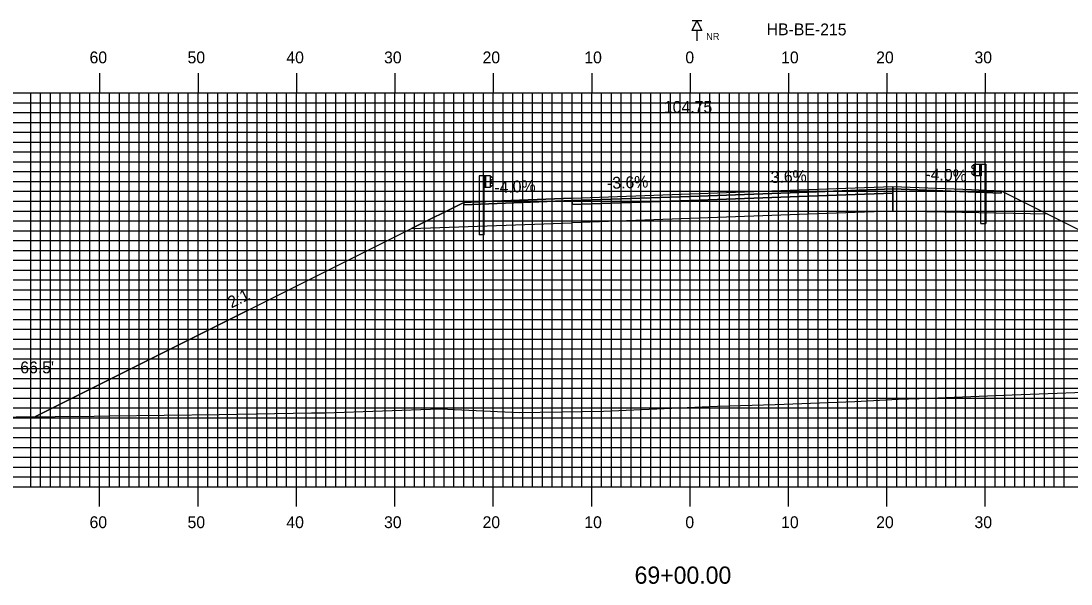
# Model space of a CAD drawing. Extents: x 1759823 to 1760167, y 442591 to 442811.
# Drawn here: x 1759921.2 to 1760027.9, y 442658.8 to 442716 of the extents above; entities that cross this region are included whole.
import ezdxf

# ---------------------------------------------------------------- set-up
doc = ezdxf.new("R2010")
doc.units = 0
for name, color, linetype in [('ANNOTATION', 7, 'Continuous'), ('BORING - NO REFUSAL', 7, 'Continuous'), ('D_Guardrail_Beam_Lt', 7, 'Continuous'), ('D_Guardrail_Beam_Rt', 7, 'Continuous'), ('D_Roadway_Centerline', 7, 'Continuous'), ('D_Roadway_Centerline_Text', 7, 'Continuous'), ('D_Roadway_Edge_Shoulder', 7, 'Continuous'), ('D_Roadway_Edge_TW', 7, 'Continuous'), ('D_Roadway_Pavement', 7, 'Continuous'), ('D_Roadway_SlopeLines', 7, 'Continuous'), ('D_Roadway_SubGrade', 7, 'Continuous'), ('D_Text_Standard', 7, 'Continuous'), ('H_V ANNOTATION', 7, 'Continuous'), ('MAJOR', 7, 'Continuous'), ('MINOR', 7, 'Continuous'), ('S_Roadway_Centerline', 7, 'Continuous')]:
    doc.layers.add(name, color=color, linetype=linetype)

msp = doc.modelspace()

# ---------------------------------------------------------------- linework, layer by layer
at = {"layer": 'BORING - NO REFUSAL'}
for p, q in [((1759990.37, 442715.97), (1759989.41, 442715.97)), ((1759989.89, 442715.01), (1759989.89, 442713.95))]:
    msp.add_line(p, q, dxfattribs=at)
msp.add_lwpolyline([(1759989.89, 442715.97), (1759990.37, 442715.01), (1759989.41, 442715.01)], close=True, dxfattribs=at)
at = {"layer": 'D_Guardrail_Beam_Lt'}
for p, q in [((1759967.76, 442700.25), (1759967.76, 442694.25)), ((1759968.23, 442700.25), (1759967.76, 442700.25)), ((1759968.92, 442700.25), (1759968.23, 442700.25)), ((1759968.23, 442700.25), (1759968.23, 442699.08)), ((1759968.29, 442700.25), (1759968.29, 442699.08)), ((1759968.4, 442700.25), (1759968.4, 442699.08)), ((1759968.92, 442699.08), (1759968.92, 442700.25)), ((1759968.92, 442700.16), (1759968.99, 442700.15)), ((1759969.15, 442699.9), (1759968.95, 442699.76)), ((1759969.01, 442700.14), (1759969.15, 442700.04)), ((1759968.23, 442699.08), (1759968.92, 442699.08)), ((1759968.25, 442694.25), (1759968.25, 442699.08)), ((1759968.92, 442699.7), (1759968.92, 442699.63)), ((1759968.99, 442699.18), (1759968.92, 442699.16)), ((1759968.95, 442699.56), (1759969.15, 442699.43)), ((1759969.15, 442699.28), (1759969.01, 442699.18)), ((1759968.25, 442694.25), (1759967.76, 442694.25))]:
    msp.add_line(p, q, dxfattribs=at)
for centre, major_axis, start_param, end_param in [((1759968.98, 442700.11), (0.0417, 0), 0.959931, 1.376053), ((1759969.1, 442699.97), (0.0877, 0), 5.323254, 7.243116), ((1759969, 442699.7), (-0.0789, 0), 5.323254, 6.283185), ((1759969, 442699.63), (-0.0789, 0), 6.283185, 7.243116), ((1759968.98, 442699.22), (0.0417, 0), 4.907132, 5.323254), ((1759969.1, 442699.36), (0.0877, 0), 5.323254, 7.243116)]:
    msp.add_ellipse(centre, major_axis=major_axis, ratio=0.995501, start_param=start_param, end_param=end_param, dxfattribs=at)
at = {"layer": 'D_Guardrail_Beam_Rt'}
for p, q in [((1760017.98, 442701.32), (1760017.84, 442701.22)), ((1760017.84, 442701.07), (1760018.03, 442700.94)), ((1760018.07, 442701.34), (1760018, 442701.32)), ((1760018.07, 442701.42), (1760018.76, 442701.42)), ((1760018.07, 442700.25), (1760018.07, 442701.42)), ((1760018.59, 442701.42), (1760018.59, 442700.25)), ((1760018.7, 442701.42), (1760018.7, 442700.25)), ((1760018.76, 442701.42), (1760019.23, 442701.42)), ((1760018.76, 442701.42), (1760018.76, 442700.25)), ((1760019.23, 442701.42), (1760019.23, 442695.42)), ((1760018.03, 442700.74), (1760017.84, 442700.6)), ((1760017.84, 442700.46), (1760017.98, 442700.36)), ((1760018, 442700.35), (1760018.07, 442700.34)), ((1760018.07, 442700.87), (1760018.07, 442700.8)), ((1760018.76, 442700.25), (1760018.07, 442700.25)), ((1760018.74, 442695.42), (1760018.74, 442700.25)), ((1760018.74, 442695.42), (1760019.23, 442695.42))]:
    msp.add_line(p, q, dxfattribs=at)
for centre, major_axis, start_param, end_param in [((1760017.89, 442701.14), (-0.0877, 0), 5.323254, 7.243116), ((1760018, 442701.28), (-0.0417, 0), 4.907132, 5.323254), ((1760017.99, 442700.87), (0.0789, 0), 0, 0.959931), ((1760017.89, 442700.53), (-0.0877, 0), 5.323254, 7.243116), ((1760018, 442700.39), (-0.0417, 0), 0.959931, 1.376053), ((1760017.99, 442700.8), (0.0789, 0), 5.323254, 6.283185)]:
    msp.add_ellipse(centre, major_axis=major_axis, ratio=0.995501, start_param=start_param, end_param=end_param, dxfattribs=at)
at = {"layer": 'D_Roadway_Centerline'}
msp.add_lwpolyline([(1759922.68, 442675.79), (1759960.89, 442694.9), (1759966.19, 442697.54), (1759969.19, 442697.66), (1759977.19, 442697.98), (1759989.19, 442698.41), (1760001.19, 442698.85), (1760009.8, 442699.16), (1760017.8, 442698.84), (1760020.8, 442698.72), (1760025.55, 442696.34), (1760059.22, 442679.5)], dxfattribs=at)
at = {"layer": 'D_Roadway_Edge_Shoulder'}
for points in [[(1760009.8, 442699.16), (1760017.8, 442698.84), (1760017.8, 442698.84), (1760020.8, 442698.72), (1760020.8, 442698.47), (1760009.8, 442698.91)], [(1759977.19, 442697.98), (1759969.19, 442697.66), (1759969.19, 442697.66), (1759966.19, 442697.54), (1759966.19, 442697.29), (1759977.19, 442697.73)]]:
    msp.add_lwpolyline(points, close=True, dxfattribs=at)
at = {"layer": 'D_Roadway_Edge_TW'}
for points in [[(1759977.19, 442697.73), (1759977.19, 442697.98), (1759989.19, 442698.41), (1760001.19, 442698.85), (1760001.19, 442698.6), (1759989.19, 442698.16)], [(1760001.19, 442698.85), (1760009.8, 442699.16), (1760009.8, 442698.91), (1760001.19, 442698.6)]]:
    msp.add_lwpolyline(points, close=True, dxfattribs=at)
at = {"layer": 'D_Roadway_Pavement'}
for points in [[(1760001.19, 442698.6), (1760009.8, 442698.91), (1760009.8, 442698.49), (1760001.19, 442698.18)], [(1759977.19, 442697.32), (1759977.19, 442697.73), (1759989.19, 442698.16), (1760001.19, 442698.6), (1760001.19, 442698.18), (1759989.19, 442697.75)]]:
    msp.add_lwpolyline(points, close=True, dxfattribs=at)
for points in [[(1760009.8, 442698.91), (1760009.8, 442698.49)], [(1760009.8, 442698.91), (1760009.8, 442698.49)], [(1759977.19, 442697.73), (1759977.19, 442697.32)]]:
    msp.add_lwpolyline(points, dxfattribs=at)
at = {"layer": 'D_Roadway_SlopeLines'}
for points in [[(1760020.8, 442698.72), (1760059.22, 442679.5)], [(1759966.19, 442697.54), (1759922.68, 442675.79)]]:
    msp.add_lwpolyline(points, dxfattribs=at)
at = {"layer": 'D_Roadway_SubGrade'}
for points in [[(1760009.8, 442698.49), (1760009.8, 442698.91), (1760020.8, 442698.47), (1760020.8, 442698.72), (1760025.55, 442696.34), (1760009.8, 442696.66)], [(1759977.19, 442697.32), (1759977.19, 442697.73), (1759966.19, 442697.29), (1759966.19, 442697.54), (1759960.89, 442694.9), (1759977.19, 442695.48)], [(1759977.19, 442695.48), (1759977.19, 442697.32), (1759989.19, 442697.75), (1760001.19, 442698.18), (1760001.19, 442696.35), (1759989.19, 442695.91)], [(1760001.19, 442698.18), (1760009.8, 442698.49), (1760009.8, 442696.66), (1760001.19, 442696.35)]]:
    msp.add_lwpolyline(points, close=True, dxfattribs=at)
at = {"layer": 'MAJOR'}
for p, q in [((1759929.19, 442710.67), (1759929.19, 442708.67)), ((1759939.19, 442710.67), (1759939.19, 442708.67)), ((1759949.19, 442710.67), (1759949.19, 442708.67)), ((1759959.19, 442710.67), (1759959.19, 442708.67)), ((1759969.19, 442710.67), (1759969.19, 442708.67)), ((1759979.19, 442710.67), (1759979.19, 442708.67)), ((1759989.19, 442710.67), (1759989.19, 442708.67)), ((1759999.19, 442710.67), (1759999.19, 442708.67)), ((1760009.19, 442710.67), (1760009.19, 442708.67)), ((1760019.19, 442710.67), (1760019.19, 442708.67)), ((1759849.19, 442708.67), (1760129.19, 442708.67)), ((1759849.19, 442708.67), (1760129.19, 442708.67)), ((1759929.19, 442668.67), (1759929.19, 442708.67)), ((1759939.19, 442668.67), (1759939.19, 442708.67)), ((1759949.19, 442668.67), (1759949.19, 442708.67)), ((1759959.19, 442668.67), (1759959.19, 442708.67)), ((1759969.19, 442668.67), (1759969.19, 442708.67)), ((1759979.19, 442668.67), (1759979.19, 442708.67)), ((1759989.19, 442668.67), (1759989.19, 442708.67)), ((1759999.19, 442668.67), (1759999.19, 442708.67)), ((1760009.19, 442668.67), (1760009.19, 442708.67)), ((1760019.19, 442668.67), (1760019.19, 442708.67)), ((1759849.19, 442703.67), (1760129.19, 442703.67)), ((1759849.19, 442698.67), (1760129.19, 442698.67)), ((1759849.19, 442693.67), (1760129.19, 442693.67)), ((1759849.19, 442688.67), (1760129.19, 442688.67)), ((1759849.19, 442683.67), (1760129.19, 442683.67)), ((1759849.19, 442678.67), (1760129.19, 442678.67)), ((1759849.19, 442673.67), (1760129.19, 442673.67)), ((1759849.19, 442668.67), (1760129.19, 442668.67)), ((1759849.19, 442668.67), (1760129.19, 442668.67)), ((1759929.19, 442666.66), (1759929.19, 442668.67)), ((1759939.19, 442666.66), (1759939.19, 442668.67)), ((1759949.19, 442666.66), (1759949.19, 442668.67)), ((1759959.19, 442666.66), (1759959.19, 442668.67)), ((1759969.19, 442666.66), (1759969.19, 442668.67)), ((1759979.19, 442666.66), (1759979.19, 442668.67)), ((1759989.19, 442666.66), (1759989.19, 442668.67)), ((1759999.19, 442666.66), (1759999.19, 442668.67)), ((1760009.19, 442666.66), (1760009.19, 442668.67)), ((1760019.19, 442666.66), (1760019.19, 442668.67))]:
    msp.add_line(p, q, dxfattribs=at)
at = {"layer": 'MINOR'}
for p, q in [((1759922.19, 442668.67), (1759922.19, 442708.67)), ((1759923.19, 442668.67), (1759923.19, 442708.67)), ((1759924.19, 442668.67), (1759924.19, 442708.67)), ((1759925.19, 442668.67), (1759925.19, 442708.67)), ((1759926.19, 442668.67), (1759926.19, 442708.67)), ((1759927.19, 442668.67), (1759927.19, 442708.67)), ((1759928.19, 442668.67), (1759928.19, 442708.67)), ((1759930.19, 442668.67), (1759930.19, 442708.67)), ((1759931.19, 442668.67), (1759931.19, 442708.67)), ((1759932.19, 442668.67), (1759932.19, 442708.67)), ((1759933.19, 442668.67), (1759933.19, 442708.67)), ((1759934.19, 442668.67), (1759934.19, 442708.67)), ((1759935.19, 442668.67), (1759935.19, 442708.67)), ((1759936.19, 442668.67), (1759936.19, 442708.67)), ((1759937.19, 442668.67), (1759937.19, 442708.67)), ((1759938.19, 442668.67), (1759938.19, 442708.67)), ((1759940.19, 442668.67), (1759940.19, 442708.67)), ((1759941.19, 442668.67), (1759941.19, 442708.67)), ((1759942.19, 442668.67), (1759942.19, 442708.67)), ((1759943.19, 442668.67), (1759943.19, 442708.67)), ((1759944.19, 442668.67), (1759944.19, 442708.67)), ((1759945.19, 442668.67), (1759945.19, 442708.67)), ((1759946.19, 442668.67), (1759946.19, 442708.67)), ((1759947.19, 442668.67), (1759947.19, 442708.67)), ((1759948.19, 442668.67), (1759948.19, 442708.67)), ((1759950.19, 442668.67), (1759950.19, 442708.67)), ((1759951.19, 442668.67), (1759951.19, 442708.67)), ((1759952.19, 442668.67), (1759952.19, 442708.67)), ((1759953.19, 442668.67), (1759953.19, 442708.67)), ((1759954.19, 442668.67), (1759954.19, 442708.67)), ((1759955.19, 442668.67), (1759955.19, 442708.67)), ((1759956.19, 442668.67), (1759956.19, 442708.67)), ((1759957.19, 442668.67), (1759957.19, 442708.67)), ((1759958.19, 442668.67), (1759958.19, 442708.67)), ((1759960.19, 442668.67), (1759960.19, 442708.67)), ((1759961.19, 442668.67), (1759961.19, 442708.67)), ((1759962.19, 442668.67), (1759962.19, 442708.67)), ((1759963.19, 442668.67), (1759963.19, 442708.67)), ((1759964.19, 442668.67), (1759964.19, 442708.67)), ((1759965.19, 442668.67), (1759965.19, 442708.67)), ((1759966.19, 442668.67), (1759966.19, 442708.67)), ((1759967.19, 442668.67), (1759967.19, 442708.67)), ((1759968.19, 442668.67), (1759968.19, 442708.67)), ((1759970.19, 442668.67), (1759970.19, 442708.67)), ((1759971.19, 442668.67), (1759971.19, 442708.67)), ((1759972.19, 442668.67), (1759972.19, 442708.67)), ((1759973.19, 442668.67), (1759973.19, 442708.67)), ((1759974.19, 442668.67), (1759974.19, 442708.67)), ((1759975.19, 442668.67), (1759975.19, 442708.67)), ((1759976.19, 442668.67), (1759976.19, 442708.67)), ((1759977.19, 442668.67), (1759977.19, 442708.67)), ((1759978.19, 442668.67), (1759978.19, 442708.67)), ((1759980.19, 442668.67), (1759980.19, 442708.67)), ((1759981.19, 442668.67), (1759981.19, 442708.67)), ((1759982.19, 442668.67), (1759982.19, 442708.67)), ((1759983.19, 442668.67), (1759983.19, 442708.67)), ((1759984.19, 442668.67), (1759984.19, 442708.67)), ((1759985.19, 442668.67), (1759985.19, 442708.67)), ((1759986.19, 442668.67), (1759986.19, 442708.67)), ((1759987.19, 442668.67), (1759987.19, 442708.67)), ((1759988.19, 442668.67), (1759988.19, 442708.67)), ((1759990.19, 442668.67), (1759990.19, 442708.67)), ((1759991.19, 442668.67), (1759991.19, 442708.67)), ((1759992.19, 442668.67), (1759992.19, 442708.67)), ((1759993.19, 442668.67), (1759993.19, 442708.67)), ((1759994.19, 442668.67), (1759994.19, 442708.67)), ((1759995.19, 442668.67), (1759995.19, 442708.67)), ((1759996.19, 442668.67), (1759996.19, 442708.67)), ((1759997.19, 442668.67), (1759997.19, 442708.67)), ((1759998.19, 442668.67), (1759998.19, 442708.67)), ((1760000.19, 442668.67), (1760000.19, 442708.67)), ((1760001.19, 442668.67), (1760001.19, 442708.67)), ((1760002.19, 442668.67), (1760002.19, 442708.67)), ((1760003.19, 442668.67), (1760003.19, 442708.67)), ((1760004.19, 442668.67), (1760004.19, 442708.67)), ((1760005.19, 442668.67), (1760005.19, 442708.67)), ((1760006.19, 442668.67), (1760006.19, 442708.67)), ((1760007.19, 442668.67), (1760007.19, 442708.67)), ((1760008.19, 442668.67), (1760008.19, 442708.67)), ((1760010.19, 442668.67), (1760010.19, 442708.67)), ((1760011.19, 442668.67), (1760011.19, 442708.67)), ((1760012.19, 442668.67), (1760012.19, 442708.67)), ((1760013.19, 442668.67), (1760013.19, 442708.67)), ((1760014.19, 442668.67), (1760014.19, 442708.67)), ((1760015.19, 442668.67), (1760015.19, 442708.67)), ((1760016.19, 442668.67), (1760016.19, 442708.67)), ((1760017.19, 442668.67), (1760017.19, 442708.67)), ((1760018.19, 442668.67), (1760018.19, 442708.67)), ((1760020.19, 442668.67), (1760020.19, 442708.67)), ((1760021.19, 442668.67), (1760021.19, 442708.67)), ((1760022.19, 442668.67), (1760022.19, 442708.67)), ((1760023.19, 442668.67), (1760023.19, 442708.67)), ((1760024.19, 442668.67), (1760024.19, 442708.67)), ((1760025.19, 442668.67), (1760025.19, 442708.67)), ((1760026.19, 442668.67), (1760026.19, 442708.67)), ((1760027.19, 442668.67), (1760027.19, 442708.67)), ((1759849.19, 442707.67), (1760129.19, 442707.67)), ((1759849.19, 442706.67), (1760129.19, 442706.67)), ((1759849.19, 442705.67), (1760129.19, 442705.67)), ((1759849.19, 442704.67), (1760129.19, 442704.67)), ((1759849.19, 442702.67), (1760129.19, 442702.67)), ((1759849.19, 442701.67), (1760129.19, 442701.67)), ((1759849.19, 442700.67), (1760129.19, 442700.67)), ((1759849.19, 442699.67), (1760129.19, 442699.67)), ((1759849.19, 442697.67), (1760129.19, 442697.67)), ((1759849.19, 442696.67), (1760129.19, 442696.67)), ((1759849.19, 442695.67), (1760129.19, 442695.67)), ((1759849.19, 442694.67), (1760129.19, 442694.67)), ((1759849.19, 442692.67), (1760129.19, 442692.67)), ((1759849.19, 442691.67), (1760129.19, 442691.67)), ((1759849.19, 442690.67), (1760129.19, 442690.67)), ((1759849.19, 442689.67), (1760129.19, 442689.67)), ((1759849.19, 442687.67), (1760129.19, 442687.67)), ((1759849.19, 442686.67), (1760129.19, 442686.67)), ((1759849.19, 442685.67), (1760129.19, 442685.67)), ((1759849.19, 442684.67), (1760129.19, 442684.67)), ((1759849.19, 442682.67), (1760129.19, 442682.67)), ((1759849.19, 442681.67), (1760129.19, 442681.67)), ((1759849.19, 442680.67), (1760129.19, 442680.67)), ((1759849.19, 442679.67), (1760129.19, 442679.67)), ((1759849.19, 442677.67), (1760129.19, 442677.67)), ((1759849.19, 442676.67), (1760129.19, 442676.67)), ((1759849.19, 442675.67), (1760129.19, 442675.67)), ((1759849.19, 442674.67), (1760129.19, 442674.67)), ((1759849.19, 442672.67), (1760129.19, 442672.67)), ((1759849.19, 442671.67), (1760129.19, 442671.67)), ((1759849.19, 442670.67), (1760129.19, 442670.67)), ((1759849.19, 442669.67), (1760129.19, 442669.67))]:
    msp.add_line(p, q, dxfattribs=at)
at = {"layer": 'S_Roadway_Centerline'}
msp.add_lwpolyline([(1759908.75, 442675.67), (1759928.63, 442675.84), (1759930.14, 442675.86), (1759941.34, 442676.02), (1759950.73, 442676.16), (1759951.3, 442676.17), (1759952.08, 442676.19), (1759963.8, 442676.59), (1759971.83, 442676.21), (1759980.39, 442676.36), (1759991.96, 442676.87), (1759997.85, 442677.03), (1760005.93, 442677.32), (1760010.34, 442677.56), (1760013.53, 442677.66), (1760021.92, 442677.99), (1760032.85, 442678.42)], dxfattribs=at)

# ---------------------------------------------------------------- texts
at = {"layer": 'ANNOTATION'}
for s, rotation, p in [('-4.0%', 357.7094, (1760013.09, 442699.83)), ('-4.0%', 2.2906, (1759969.32, 442698.47)), ('-3.6%', 2.0618, (1759980.77, 442698.91)), ('3.6%', 2.0618, (1759997.4, 442699.51)), ('2:1', 26.5651, (1759942.58, 442686.77))]:
    msp.add_text(s, height=1.2, rotation=rotation, dxfattribs=at).set_placement(p)
at = {"layer": 'BORING - NO REFUSAL'}
msp.add_text('HB-BE-215', height=1.2, rotation=359.8142, dxfattribs=at).set_placement((1759996.97, 442714.53))
msp.add_text('NR', height=0.7, dxfattribs=at).set_placement((1759990.82, 442714.05))
at = {"layer": 'D_Roadway_Centerline'}
for s, p in [('C', (1759989.18, 442698.41)), ('L', (1759989.19, 442698.41))]:
    msp.add_text(s, height=0.0146, dxfattribs=at).set_placement(p)
at = {"layer": 'D_Roadway_Centerline_Text'}
msp.add_text('104.75', height=1.2, dxfattribs=at).set_placement((1759986.53, 442706.64))
at = {"layer": 'D_Text_Standard'}
msp.add_text("66.5'", height=1.2, dxfattribs=at).set_placement((1759921.12, 442680.19))
at = {"layer": 'H_V ANNOTATION'}
for s, height, p in [('60', 1.2, (1759928.16, 442711.67)), ('50', 1.2, (1759938.12, 442711.67)), ('40', 1.2, (1759948.16, 442711.67)), ('30', 1.2, (1759958.09, 442711.67)), ('20', 1.2, (1759968.1, 442711.67)), ('10', 1.2, (1759978.44, 442711.67)), ('0', 1.2, (1759988.71, 442711.67)), ('10', 1.2, (1759998.44, 442711.67)), ('20', 1.2, (1760008.1, 442711.67)), ('30', 1.2, (1760018.09, 442711.67)), ('60', 1.2, (1759928.16, 442664.47)), ('50', 1.2, (1759938.12, 442664.47)), ('40', 1.2, (1759948.16, 442664.47)), ('30', 1.2, (1759958.09, 442664.47)), ('20', 1.2, (1759968.1, 442664.47)), ('10', 1.2, (1759978.44, 442664.47)), ('0', 1.2, (1759988.71, 442664.47)), ('10', 1.2, (1759998.44, 442664.47)), ('20', 1.2, (1760008.1, 442664.47)), ('30', 1.2, (1760018.09, 442664.47)), ('69+00.00', 1.75, (1759983.55, 442658.82))]:
    msp.add_text(s, height=height, dxfattribs=at).set_placement(p)

doc.saveas('drawing.dxf')
